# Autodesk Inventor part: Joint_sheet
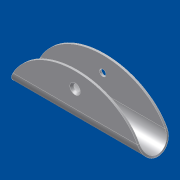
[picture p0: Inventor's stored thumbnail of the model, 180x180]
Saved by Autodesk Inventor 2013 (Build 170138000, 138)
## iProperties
Shininess: 69.0
Length Units: 11269
Angle Units: 11279
Time Units: 11290
Mass Units: 11283
Length Display Precision: 3
Angle Display Precision: 2
Created: 2001-04
Part Number: Joint_sheet
Material: Standard
Document SubType Name: Modellieren
Designer: dl
Density: 1 g/cm^3
Sheet Metal Rule: Norm
Density: 0.0
Volumn: 0.0
Area: 0.0
PropertySet Name: Model Information
Control State: 0
Master: False
Checked Out: False
Author: dl
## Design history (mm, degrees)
sketch "Sketch2"
  geometry: L1 (68.5, 0)-(-68.5, 0); 1 further point; 1 other entity
  constraints: 2 end point, 1 horizontal, 1 midpoint, 3 other
feature "Freie Lasche1" sketch "Sketch2" dims "d12" = 180 deg, "d13" = 13, "d23" = 2 (= BreiteBiegungsfreistellung), "d24" = 1 (= TiefeBiegungsfreistellung), "d25" = 4 (= MinimalRest), "Objekthöhe" = 2
body "Solid1"
node "Fläche1"
sketch "Sketch3"
  geometry: C1 r 3.1 at (62.786, 17.5) reference; 1 further point
  constraints: 1 coincident
hole "Hole1" sketch "Sketch3" diameter "d14" = 6.6; stored, may be unused: countersink angle "d18" = 60 deg, drill point angle "d20" = 118 deg; dims "d15" = 6, "d16" = 4, "d17" = 2, "d19" = 8
chamfer "Chamfer1" distance "d21" = 2; stored, may be unused: second distance "d22" = 2, angle "d26" = 45 deg
sketch "Sketch1"
  geometry: L1 (0, -55)-(0, 55); L2 (68.5, 0)-(-68.5, 0); 1 further point; 1 other entity
  constraints: 4 end point, 2 midpoint, 1 horizontal, 1 vertical, 6 other
  dimensions: "d0" = 137 distance of L2.start L2.end; "d1" = 110 distance of L1.start L1.end
feature "Platte1" dims "Objekthöhe" = 2
other parameters: "Biegeradius" = 2 (= Objekthöhe), "BreiteBiegungsfreistellung" = 2 (= Objekthöhe), "TiefeBiegungsfreistellung" = 1 (= 0.5 x Objekthöhe), "GrößeEckenfreistellung" = 8 (= 4 x Objekthöhe), "AbstandVerbindung" = 0.01, "MinimalRest" = 4 (= 2 x Objekthöhe), "d2" = 2 (= Biegeradius), "Übergangsradius" = 2 (= Biegeradius), "JacobiRadiusSize" = 2 (= Objekthöhe), "GapSize" = 2 (= Objekthöhe)
